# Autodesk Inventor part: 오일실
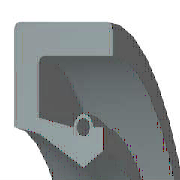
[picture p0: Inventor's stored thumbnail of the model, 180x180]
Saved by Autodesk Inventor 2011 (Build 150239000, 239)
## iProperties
IsCustomPart: 1
Company: 한국ATC센터
Created: 2014-11
Part Number: 오일실
Material: 고무
Description: 오일-실
Document SubType Name: Modeling
Standard: KS B 2804
Designer: KYOUNG IL JANG
Standards Organization: KS
Language: ko-KR
Size Designation: S - 25 40 8
Categories: <MemberInstance><Categories><Category DisplayName="샤프트 부품" InternalName="7f7aeb1f-a693-4053-b835-cee3144e0d98" Mnemonic="SHFT"><Category DisplayName="실링" Intern
Density: 0.93 g/cm^3
Mass: 2.48215 g
Surface Area: 40.3381 cm^2
Volume: 2.66898 cm^3
Author: KYOUNG IL JANG
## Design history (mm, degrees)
revolve "본체" stored, may be unused: angle "d17" = 90 deg
revolve "스프링1" stored, may be unused: angle "d18" = 90 deg
body "Solid1"
sketch "스케치1"
  geometry: L1 (0, 20)-(8, 20); L2 (8, 20)-(8, 18.75); L3 (8, 18.75)-(1.75, 18.75); L4 (0, 20)-(0, 14.6); L5 (0, 14.6)-(1.75, 14.25); L6 (1.75, 14.25)-(4.9, 12.5); L7 (4.9, 12.5)-(0, 12.5); L8 (6.3, 13.375)-(6.3, 14.6); L9 (0, 0)-(9.586, 0) reference; L10 (4.9, 12.5)-(6.3, 13.375); L11 (0, 18)-(0, -3) reference; L12 (-1.917, 0)-(11.503, 0) reference; L13 (4.2, 14.6)-(1.75, 15.09); L14 (1.75, 15.09)-(1.75, 18.75); L15 (6.3, 14.6)-(5.6, 14.6); C1 r 0.455 at (4.9, 14.6); A1 r 0.7 centre (4.9, 14.6) between (5.6, 14.6) and (4.2, 14.6)
  constraints: 26 end point, 5 horizontal alignment, 4 perpendicular, 2 centre point, 2 collinear, 2 horizontal, 2 parallel, 2 point on circle, 2 point on line, 2 vertical alignment, 1 coincident
  dimensions: "d0" = 40 diameter of L1 L9 (= SD2); "d1" = 26.75 diameter of L8.start L9 (= ABDM); "d2" = 1.25 distance of L1.end L2.end (computed from SD); "d3" = 0.91 diameter of C1 (= SPDI); "d4" = 1.4 diameter of A1 (= SPDA); "d5" = 25 diameter of L6.end L9 (= NND); "d6" = 28.5 diameter of L5.end L9 (= TKDM); "d7" = 29.2 diameter of L4.end L9 (= HLDM); "d8" = 4.9 distance from line of C1.centre L4 (= SPDST); "d9" = 6.3 distance between parallel lines of L8 L4 (= SDI); "d10" = 8 distance between parallel lines of L2 L4 (= SWDT); "d12" = 1.75 distance between parallel lines of L14 L4 (= SD)
fillet "모깎기1" dims "d11" = 0.3 (= RR)
other parameters: "SD2" = 40 [user parameter; used in 1 equation term], "SWDT" = 8 [user parameter; used in 1 equation term], "RR" = 0.3 [user parameter; used in 1 equation term], "SD" = 1.75 [user parameter; used in 2 equation terms], "NND" = 25 [user parameter; used in 1 equation term], "SPDA" = 1.4 [user parameter; used in 1 equation term], "SPDI" = 0.91 [user parameter; used in 1 equation term], "TKDM" = 28.5 [user parameter; used in 1 equation term], "HLDM" = 29.2 [user parameter; used in 1 equation term], "ABDM" = 26.75 [user parameter; used in 1 equation term], "SDI" = 6.3 [user parameter; used in 1 equation term], "SPDST" = 4.9 [user parameter; used in 1 equation term], "d13" = 0, "d14" = 0, "d15" = 0, "LAB" = 0.35 [user parameter]
